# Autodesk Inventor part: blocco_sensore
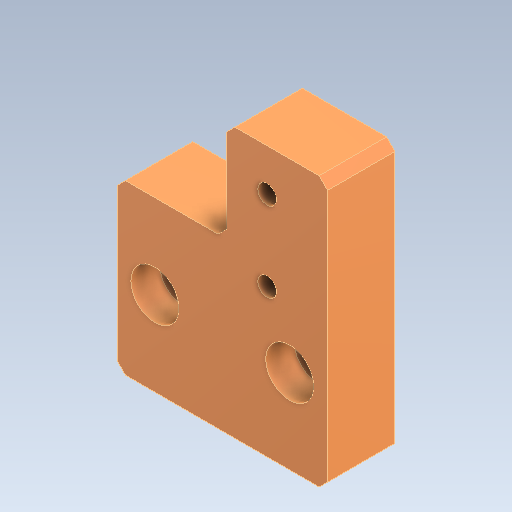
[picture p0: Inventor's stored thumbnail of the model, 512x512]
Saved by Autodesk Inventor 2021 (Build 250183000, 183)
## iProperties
Created: 2026-01
Part Number: blocco_sensore
Material: Plastica ABS
Document SubType Name: Modeling
Designer: hp
Density: 1.06 g/cm^3
Appearance: Default
Author: hp
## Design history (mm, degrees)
feature "Solido1"
body "Solid1"
